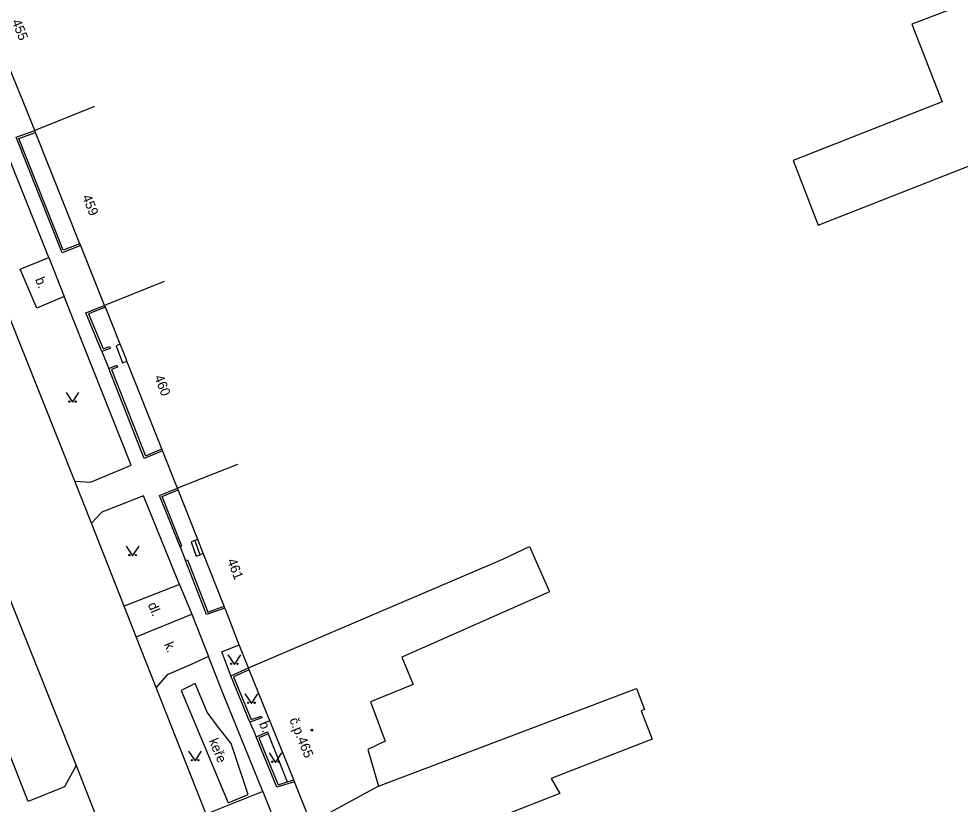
# Model space of a CAD drawing. Extents: x -577457 to -568404, y -1208466 to -1201387.
# Drawn here: x -575197.2 to -575124, y -1204657 to -1204595.9 of the extents above; entities that cross this region are included whole.
import ezdxf

# ---------------------------------------------------------------- set-up
doc = ezdxf.new("R2010")
doc.units = 0
for name, color, linetype in [('BUDOVY_MĚŘ', 7, 'Continuous'), ('BUDOVY_NEMĚŘ', 7, 'Continuous'), ('POMOC_POPIS', 7, 'Continuous'), ('ROZHRANÍ_PLOCH', 7, 'Continuous'), ('ZELEŇ', 7, 'Continuous'), ('ZN_BUDOV', 7, 'Continuous'), ('ZN_DOPLŇKOVÉ', 7, 'Continuous'), ('ZN_KULTUR', 7, 'Continuous'), ('Č_POPIS_ORIENT', 7, 'Continuous')]:
    doc.layers.add(name, color=color, linetype=linetype)

msp = doc.modelspace()

# ---------------------------------------------------------------- linework, layer by layer
at = {"layer": 'BUDOVY_MĚŘ'}
for points in [[(-575196, -1204604.54), (-575196.86, -1204602.42)], [(-575191.36, -1204602.68), (-575196, -1204604.54)], [(-575195.94, -1204604.69), (-575196, -1204604.54)], [(-575192.49, -1204613.35), (-575195.94, -1204604.69)], [(-575192.43, -1204613.5), (-575192.49, -1204613.35)], [(-575192.37, -1204613.64), (-575192.43, -1204613.5)], [(-575190.57, -1204618.15), (-575191.35, -1204616.19)], [(-575185.93, -1204616.29), (-575190.57, -1204618.15)], [(-575190.51, -1204618.3), (-575190.57, -1204618.15)], [(-575189.36, -1204621.17), (-575190.51, -1204618.3)], [(-575189.29, -1204621.36), (-575189.36, -1204621.17)], [(-575188.83, -1204622.49), (-575188.9, -1204622.31)], [(-575186.11, -1204629.31), (-575188.83, -1204622.49)], [(-575186.05, -1204629.46), (-575186.11, -1204629.31)], [(-575185.98, -1204629.64), (-575186.05, -1204629.46)], [(-575180.23, -1204630.53), (-575184.89, -1204632.36)], [(-575184.89, -1204632.36), (-575185.07, -1204631.92)], [(-575184.83, -1204632.5), (-575184.89, -1204632.36)], [(-575183.31, -1204636.36), (-575184.83, -1204632.5)], [(-575182.89, -1204637.44), (-575183.31, -1204636.36)], [(-575181.27, -1204641.56), (-575182.89, -1204637.44)], [(-575181.21, -1204641.7), (-575181.27, -1204641.56)], [(-575181.14, -1204641.87), (-575181.21, -1204641.7)], [(-575180.09, -1204644.56), (-575180.14, -1204644.43)], [(-575179.38, -1204646.35), (-575180.09, -1204644.56)], [(-575179.32, -1204646.5), (-575179.38, -1204646.35)], [(-575175.85, -1204655.06), (-575179.32, -1204646.5)], [(-575175.79, -1204655.21), (-575175.85, -1204655.06)]]:
    msp.add_lwpolyline(points, dxfattribs=at)
at = {"layer": 'BUDOVY_NEMĚŘ'}
for points in [[(-575117.1, -1204592.23), (-575127.73, -1204596.26), (-575125.38, -1204602.31), (-575136.98, -1204606.89), (-575135.02, -1204611.92), (-575112.3, -1204602.98)], [(-575159.57, -1204637.91), (-575157.5, -1204636.91), (-575155.94, -1204640.43), (-575167.42, -1204645.53), (-575166.54, -1204647.66), (-575169.87, -1204648.99), (-575168.72, -1204652.06), (-575170.07, -1204652.7), (-575169.25, -1204655.55)], [(-575179.38, -1204646.35), (-575159.57, -1204637.91)], [(-575169.25, -1204655.55), (-575149.18, -1204647.97), (-575148.54, -1204649.6), (-575148.81, -1204649.71), (-575147.95, -1204651.89), (-575155.8, -1204654.97), (-575155.13, -1204656.14), (-575162.77, -1204659.11), (-575162.17, -1204660.72), (-575165.96, -1204662.17), (-575164.16, -1204666.53)], [(-575169.25, -1204655.55), (-575174.5, -1204658.4)]]:
    msp.add_lwpolyline(points, dxfattribs=at)
at = {"layer": 'ROZHRANÍ_PLOCH'}
for points in [[(-575194.92, -1204614.42), (-575199.19, -1204603.8), (-575200.25, -1204603.84), (-575202.37, -1204604.68), (-575203.33, -1204605.65)], [(-575192.89, -1204631.84), (-575203.33, -1204605.65)], [(-575193.72, -1204617.46), (-575195.83, -1204618.38), (-575197.13, -1204615.33), (-575194.92, -1204614.42)], [(-575194.92, -1204614.42), (-575193.72, -1204617.46)], [(-575192.89, -1204631.84), (-575191.66, -1204631.91), (-575188.51, -1204630.58), (-575193.72, -1204617.46)], [(-575206.29, -1204620.13), (-575192.79, -1204653.96)], [(-575189.36, -1204621.17), (-575189.68, -1204621.3), (-575189.17, -1204622.62), (-575188.83, -1204622.49)], [(-575192.79, -1204653.96), (-575193.7, -1204655.62), (-575196.52, -1204656.76), (-575204.78, -1204635.79), (-575210.24, -1204621.86)], [(-575191.58, -1204635.09), (-575192.89, -1204631.84)], [(-575184.73, -1204639.88), (-575187.53, -1204632.96), (-575190.79, -1204634.23), (-575191.58, -1204635.09)], [(-575189.04, -1204641.56), (-575191.58, -1204635.09)], [(-575183.55, -1204636.45), (-575183.83, -1204636.56), (-575183.44, -1204637.66), (-575183.16, -1204637.55)], [(-575183.31, -1204636.36), (-575183.55, -1204636.45)], [(-575183.55, -1204636.45), (-575183.16, -1204637.55)], [(-575183.16, -1204637.55), (-575182.89, -1204637.44)], [(-575184.73, -1204639.88), (-575189.04, -1204641.56)], [(-575184.73, -1204639.88), (-575183.77, -1204642.18)], [(-575188.11, -1204643.93), (-575189.04, -1204641.56)], [(-575188.11, -1204643.93), (-575183.77, -1204642.18)], [(-575183.77, -1204642.18), (-575182.48, -1204645.47)], [(-575186.56, -1204647.87), (-575188.11, -1204643.93)], [(-575180.75, -1204646.98), (-575181.45, -1204645.1), (-575180.09, -1204644.56)], [(-575183.84, -1204646.09), (-575185.71, -1204646.9), (-575186.56, -1204647.87)], [(-575182.48, -1204645.47), (-575183.84, -1204646.09)], [(-575181.33, -1204648.38), (-575182.48, -1204645.47)], [(-575182.65, -1204657.75), (-575186.56, -1204647.87)], [(-575178.26, -1204655.97), (-575181.33, -1204648.38)], [(-575177.84, -1204651.49), (-575176.36, -1204655.23)], [(-575192.79, -1204653.96), (-575190.84, -1204658.91)], [(-575178.26, -1204655.97), (-575182.65, -1204657.75)], [(-575178.26, -1204655.97), (-575177.14, -1204658.81)]]:
    msp.add_lwpolyline(points, dxfattribs=at)
at = {"layer": 'ZELEŇ'}
msp.add_lwpolyline([(-575183.53, -1204647.58), (-575184.61, -1204648.11), (-575180.96, -1204656.85), (-575179.39, -1204656.2), (-575180.72, -1204652.24), (-575181.78, -1204650.9), (-575182.59, -1204649.79), (-575183.53, -1204647.58)], dxfattribs=at)
at = {"layer": 'ZN_BUDOV'}
msp.add_circle((-575174.44, -1204651.2), 0.0875, dxfattribs=at)
at = {"layer": 'ZN_DOPLŇKOVÉ'}
for points in [[(-575196.86, -1204602.42), (-575197.88, -1204599.88)], [(-575192.43, -1204613.5), (-575193.87, -1204614.06), (-575197.44, -1204605.07), (-575196, -1204604.54)], [(-575192.49, -1204613.35), (-575193.78, -1204613.85), (-575197.24, -1204605.17), (-575195.94, -1204604.69)], [(-575191.35, -1204616.19), (-575192.37, -1204613.64)], [(-575190.78, -1204621.75), (-575192.02, -1204618.72), (-575190.57, -1204618.15)], [(-575190.51, -1204618.3), (-575191.81, -1204618.81), (-575190.69, -1204621.54), (-575190.19, -1204621.35), (-575190.14, -1204621.5), (-575190.78, -1204621.75)], [(-575190.78, -1204621.75), (-575190.25, -1204623.06)], [(-575188.9, -1204622.31), (-575189.29, -1204621.36)], [(-575190.25, -1204623.06), (-575189.62, -1204622.81), (-575189.56, -1204622.96), (-575190.04, -1204623.15), (-575187.39, -1204629.85), (-575186.11, -1204629.31)], [(-575186.05, -1204629.46), (-575187.48, -1204630.06), (-575190.25, -1204623.06)], [(-575185.07, -1204631.92), (-575185.98, -1204629.64)], [(-575184.69, -1204636.93), (-575186.29, -1204632.94), (-575184.89, -1204632.36)], [(-575184.69, -1204636.93), (-575184.55, -1204636.88), (-575186.09, -1204633.02), (-575184.83, -1204632.5)], [(-575184.69, -1204636.93), (-575184.26, -1204638.01)], [(-575184.26, -1204638.01), (-575184.12, -1204637.96), (-575182.54, -1204642.01), (-575181.27, -1204641.56)], [(-575181.21, -1204641.7), (-575182.63, -1204642.2), (-575184.26, -1204638.01)], [(-575180.14, -1204644.43), (-575181.14, -1204641.87)], [(-575180.75, -1204646.98), (-575179.38, -1204646.35)], [(-575179.32, -1204646.5), (-575180.54, -1204647.06), (-575179.17, -1204650.38), (-575178.38, -1204650.1), (-575178.32, -1204650.25), (-575179.26, -1204650.58)], [(-575179.26, -1204650.58), (-575180.75, -1204646.98)], [(-575179.26, -1204650.58), (-575178.78, -1204651.72)], [(-575178.78, -1204651.72), (-575177.9, -1204651.34), (-575177.84, -1204651.49)], [(-575175.79, -1204655.21), (-575177.15, -1204655.65), (-575178.78, -1204651.72)], [(-575177.84, -1204651.49), (-575178.57, -1204651.8), (-575177.05, -1204655.45), (-575176.36, -1204655.23)], [(-575176.36, -1204655.23), (-575175.85, -1204655.06)], [(-575174.79, -1204657.68), (-575175.79, -1204655.21)]]:
    msp.add_lwpolyline(points, dxfattribs=at)
at = {"layer": 'ZN_KULTUR'}
for points in [[(-575193.57, -1204624.94), (-575193.07, -1204625.69), (-575192.57, -1204624.94)], [(-575188.89, -1204636.88), (-575188.39, -1204637.63), (-575187.89, -1204636.88)], [(-575180.97, -1204645.35), (-575180.47, -1204646.1), (-575179.97, -1204645.35)], [(-575179.64, -1204648.37), (-575179.14, -1204649.12), (-575178.64, -1204648.37)], [(-575184.03, -1204652.84), (-575183.53, -1204653.59), (-575183.03, -1204652.84)], [(-575177.77, -1204652.96), (-575177.27, -1204653.71), (-575176.77, -1204652.96)]]:
    msp.add_lwpolyline(points, dxfattribs=at)
for centre in [(-575193.32, -1204625.64), (-575192.82, -1204625.64), (-575188.64, -1204637.58), (-575188.14, -1204637.58), (-575180.72, -1204646.05), (-575180.22, -1204646.05), (-575179.39, -1204649.07), (-575178.89, -1204649.07), (-575183.78, -1204653.54), (-575183.28, -1204653.54), (-575177.52, -1204653.66), (-575177.02, -1204653.66)]:
    msp.add_circle(centre, 0.05, dxfattribs=at)

# ---------------------------------------------------------------- texts
at = {"layer": 'POMOC_POPIS'}
for s, rotation, p in [('b.', 291.76002, (-575195.99, -1204616.12)), ('dl.', 292.42998, (-575187.22, -1204641.43)), ('k.', 292.42998, (-575185.95, -1204644.52)), ('b.', 291.5898, (-575178.55, -1204650.68))]:
    msp.add_text(s, height=0.75, rotation=rotation, dxfattribs=at).set_placement(p)
at = {"layer": 'ZELEŇ'}
msp.add_text('keře', height=0.75, rotation=292.66638, dxfattribs=at).set_placement((-575182.47, -1204652.02))
at = {"layer": 'Č_POPIS_ORIENT'}
for s, rotation, p in [('455', 292.01997, (-575197.81, -1204596.06)), ('459', 291.76002, (-575192.33, -1204609.7)), ('460', 291.80001, (-575186.72, -1204623.73)), ('461', 291.46999, (-575181.05, -1204638.01)), ('č.p.465', 292.06002, (-575176.2, -1204650.39))]:
    msp.add_text(s, height=0.75, rotation=rotation, dxfattribs=at).set_placement(p)

doc.saveas('drawing.dxf')
